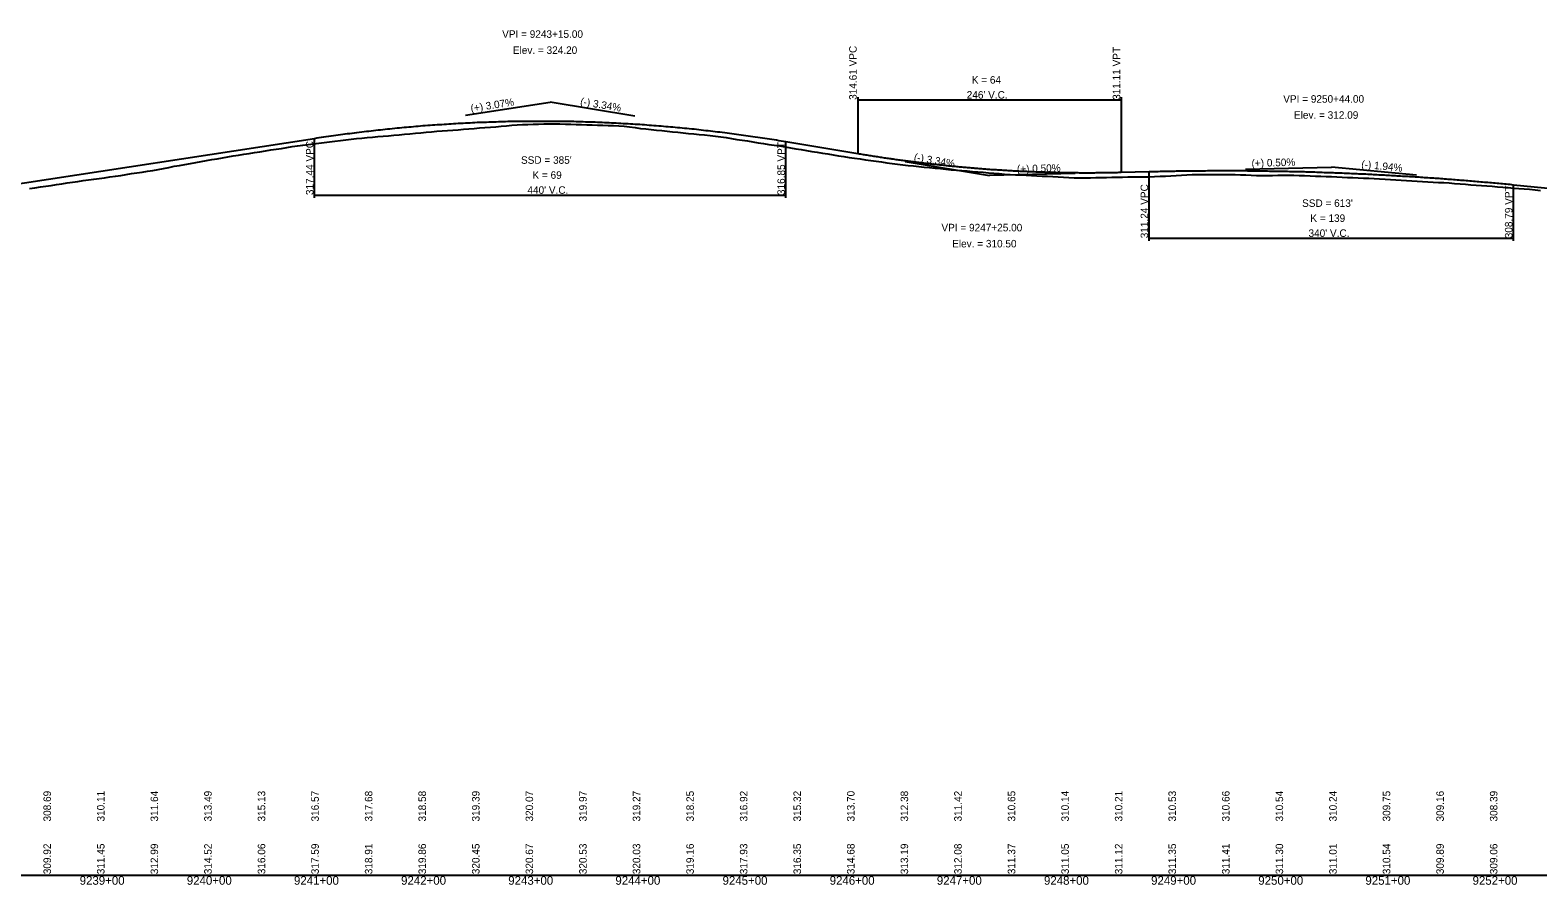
# Model space of a CAD drawing. Extents: x 1838386 to 1955906, y 719739 to 834437.
# Drawn here: x 1918084 to 1919492, y 738480 to 739277 of the extents above; entities that cross this region are included whole.
import ezdxf

# ---------------------------------------------------------------- set-up
doc = ezdxf.new("R2010")
doc.units = 0
for name, color, linetype in [('RD_DDB_GradeTX', 7, 'Continuous'), ('RD_DDB_Profile_EX', 7, 'Continuous'), ('RD_DDB_Profile_Lbl', 7, 'Continuous'), ('RD_DDB_Profile_PR', 7, 'Continuous'), ('RD_DDB_StaTX', 7, 'Continuous'), ('RD_DDB_StripGrade', 7, 'Continuous'), ('RD_DDB_VCLbl', 7, 'Continuous'), ('RD_GPK_Profile_Cell', 7, 'Continuous')]:
    doc.layers.add(name, color=color, linetype=linetype)

msp = doc.modelspace()

# ---------------------------------------------------------------- linework, layer by layer
at = {"layer": 'RD_DDB_GradeTX'}
for p, q in [((1918490.8, 739198), (1918569.9, 739210.1)), ((1918648.8, 739196.9), (1918569.9, 739210.1)), ((1918901, 739154.8), (1918979.9, 739141.6)), ((1919218.9, 739147.6), (1919298.9, 739149.6)), ((1919378.5, 739141.9), (1919298.9, 739149.6)), ((1919059.9, 739143.6), (1918979.9, 739141.6))]:
    msp.add_line(p, q, dxfattribs=at)
at = {"layer": 'RD_DDB_Profile_EX'}
for points in [[(1918084, 739129.5), (1918089, 739130.2), (1918094, 739131), (1918099, 739131.7), (1918104, 739132.5), (1918109, 739133.2), (1918114, 739133.9), (1918119, 739134.7), (1918124, 739135.4), (1918129, 739136.1), (1918134, 739136.9), (1918139, 739137.6), (1918144, 739138.4), (1918149, 739139), (1918154, 739139.6), (1918159, 739140.3), (1918164, 739141.1), (1918169, 739141.8), (1918174, 739142.6), (1918179, 739143.4), (1918184, 739144.1), (1918189, 739144.9), (1918194, 739145.6), (1918199, 739146.3), (1918204, 739147.2), (1918209, 739148.2), (1918214, 739149.2), (1918219, 739150.3), (1918224, 739151.1), (1918229, 739152), (1918234, 739152.9), (1918239, 739153.8), (1918244, 739154.7), (1918249, 739155.6), (1918254, 739156.5), (1918259, 739157.3), (1918264, 739158.2), (1918269, 739159.1), (1918274, 739159.9), (1918279, 739160.7), (1918284, 739161.5), (1918289, 739162.3), (1918294, 739163.1), (1918299, 739163.9), (1918304, 739164.7), (1918309, 739165.5), (1918314, 739166.2), (1918319, 739167), (1918324, 739167.8), (1918329, 739168.6), (1918334, 739169.4), (1918339, 739170.1), (1918344, 739170.7), (1918349, 739171.3), (1918354, 739171.9), (1918359, 739172.5), (1918364, 739173.1), (1918369, 739173.7), (1918374, 739174.3), (1918379, 739174.9), (1918384, 739175.5), (1918389, 739176.1), (1918394, 739176.5), (1918399, 739177), (1918404, 739177.4), (1918409, 739177.9), (1918414, 739178.3), (1918419, 739178.8), (1918424, 739179.3), (1918429, 739179.7), (1918434, 739180.2), (1918439, 739180.6), (1918444, 739181.1), (1918449, 739181.5), (1918454, 739182), (1918459, 739182.4), (1918464, 739182.9), (1918469, 739183.3), (1918474, 739183.7), (1918479, 739184.1), (1918484, 739184.4), (1918489, 739184.8), (1918494, 739185.2), (1918499, 739185.6), (1918504, 739186), (1918509, 739186.4), (1918514, 739186.8), (1918519, 739187.2), (1918524, 739187.6), (1918529, 739188.1), (1918534, 739188.7), (1918539, 739189), (1918544, 739189.1)], [(1918544, 739189.1), (1918549, 739189.3), (1918554, 739189.5), (1918559, 739189.6), (1918564, 739189.8), (1918569, 739189.9), (1918574, 739190), (1918579, 739189.8), (1918584, 739189.7), (1918589, 739189.5), (1918594, 739189.3), (1918599, 739189.2), (1918604, 739189), (1918609, 739188.8), (1918614, 739188.7), (1918619, 739188.5), (1918624, 739188.3), (1918629, 739188.2), (1918634, 739188), (1918639, 739187.8), (1918644, 739187.2), (1918649, 739186.3), (1918654, 739185.6), (1918659, 739185.1), (1918664, 739184.6), (1918669, 739184.1), (1918674, 739183.6), (1918679, 739183), (1918684, 739182.5), (1918689, 739182), (1918694, 739181.5), (1918699, 739181), (1918704, 739180.5), (1918709, 739180), (1918714, 739179.5), (1918719, 739178.9), (1918724, 739178.4), (1918729, 739177.7), (1918734, 739177), (1918739, 739176.2), (1918744, 739175.4), (1918749, 739174.6), (1918754, 739173.9), (1918759, 739173.1), (1918764, 739172.3), (1918769, 739171.5), (1918774, 739170.7), (1918779, 739169.9), (1918784, 739169.2), (1918789, 739168.4), (1918794, 739167.6), (1918799, 739166.7), (1918804, 739165.9), (1918809, 739165.1), (1918814, 739164.2), (1918819, 739163.4), (1918824, 739162.6), (1918829, 739161.8), (1918834, 739160.9), (1918839, 739160.1), (1918844, 739159.3), (1918849, 739158.5), (1918854, 739157.8), (1918859, 739157.1), (1918864, 739156.4), (1918869, 739155.7), (1918874, 739155), (1918879, 739154.3), (1918884, 739153.6), (1918889, 739152.9), (1918894, 739152.2), (1918899, 739151.6), (1918904, 739151.1), (1918909, 739150.6), (1918914, 739150.1), (1918919, 739149.6), (1918924, 739149.1), (1918929, 739148.6), (1918934, 739148.1), (1918939, 739147.5), (1918944, 739147.1), (1918949, 739146.7), (1918954, 739146.3), (1918959, 739145.9), (1918964, 739145.5), (1918969, 739145.1), (1918974, 739144.7), (1918979, 739144.2), (1918984, 739143.8), (1918989, 739143.4), (1918994, 739143), (1918999, 739142.7), (1919004, 739142.4), (1919009, 739142.2), (1919014, 739141.9), (1919019, 739141.7), (1919024, 739141.4), (1919029, 739141.2), (1919034, 739140.9), (1919039, 739140.7), (1919044, 739140.4)], [(1919044, 739140.4), (1919049, 739140.1), (1919054, 739139.9), (1919059, 739139.6), (1919064, 739139.4), (1919069, 739139.5), (1919074, 739139.6), (1919079, 739139.7), (1919084, 739139.8), (1919089, 739139.9), (1919094, 739140), (1919099, 739140.1), (1919104, 739140.2), (1919109, 739140.3), (1919114, 739140.3), (1919119, 739140.4), (1919124, 739140.4), (1919129, 739140.5), (1919134, 739140.7), (1919139, 739140.9), (1919144, 739141.2), (1919149, 739141.5), (1919154, 739141.7), (1919159, 739142), (1919164, 739142.3), (1919169, 739142.5), (1919174, 739142.7), (1919179, 739142.7), (1919184, 739142.6), (1919189, 739142.6), (1919194, 739142.6), (1919199, 739142.5), (1919204, 739142.5), (1919209, 739142.5), (1919214, 739142.4), (1919219, 739142.2), (1919224, 739142), (1919229, 739141.8), (1919234, 739141.7), (1919239, 739141.8), (1919244, 739141.8), (1919249, 739141.9), (1919254, 739141.9), (1919259, 739141.9), (1919264, 739141.9), (1919269, 739141.8), (1919274, 739141.6), (1919279, 739141.4), (1919284, 739141.2), (1919289, 739141), (1919294, 739140.8), (1919299, 739140.6), (1919304, 739140.4), (1919309, 739140.2), (1919314, 739139.9), (1919319, 739139.7), (1919324, 739139.5), (1919329, 739139.3), (1919334, 739139.1), (1919339, 739138.8), (1919344, 739138.5), (1919349, 739138.2), (1919354, 739138), (1919359, 739137.7), (1919364, 739137.4), (1919369, 739137.1), (1919374, 739136.8), (1919379, 739136.5), (1919384, 739136.2), (1919389, 739135.9), (1919394, 739135.6), (1919399, 739135.3), (1919404, 739135), (1919409, 739134.7), (1919414, 739134.3), (1919419, 739133.9), (1919424, 739133.5), (1919429, 739133.1), (1919434, 739132.8), (1919439, 739132.4), (1919444, 739132), (1919449, 739131.6), (1919454, 739131.2), (1919459, 739130.8), (1919464, 739130.4), (1919469, 739130), (1919474, 739129.6), (1919479, 739129.3), (1919484, 739128.8), (1919489, 739128.3), (1919494, 739127.8)]]:
    msp.add_lwpolyline(points, dxfattribs=at)
at = {"layer": 'RD_DDB_Profile_PR'}
for p, q in [((1918029.9, 739127.2), (1918349.9, 739176.3)), ((1918789.9, 739173.4), (1918856.9, 739162.2)), ((1919102.9, 739144.7), (1919128.9, 739145.4)), ((1919468.9, 739133.1), (1919738.9, 739106.9))]:
    msp.add_line(p, q, dxfattribs=at)
for points in [[(1918349.9, 739176.3), (1918358.7, 739177.7), (1918367.5, 739178.9), (1918376.3, 739180.1), (1918385.1, 739181.3), (1918393.9, 739182.4), (1918402.7, 739183.4), (1918411.5, 739184.4), (1918420.3, 739185.3), (1918429.1, 739186.2), (1918437.9, 739187), (1918446.7, 739187.8), (1918455.5, 739188.5), (1918464.3, 739189.1), (1918473.1, 739189.7), (1918481.9, 739190.3), (1918490.7, 739190.7), (1918499.5, 739191.2), (1918508.3, 739191.5), (1918517.1, 739191.8), (1918525.9, 739192.1), (1918534.7, 739192.3), (1918543.5, 739192.4), (1918552.3, 739192.5), (1918561.1, 739192.5), (1918569.9, 739192.5), (1918578.7, 739192.4), (1918587.5, 739192.3), (1918596.3, 739192.1), (1918605.1, 739191.8), (1918613.9, 739191.5), (1918622.7, 739191.1), (1918631.5, 739190.7), (1918640.3, 739190.2), (1918649.1, 739189.7), (1918657.9, 739189.1), (1918666.7, 739188.4), (1918675.5, 739187.7), (1918684.3, 739187), (1918693.1, 739186.1), (1918701.9, 739185.3), (1918710.7, 739184.3), (1918719.5, 739183.3), (1918728.3, 739182.3), (1918737.1, 739181.2), (1918745.9, 739180), (1918754.7, 739178.8), (1918763.5, 739177.5), (1918772.3, 739176.2), (1918781.1, 739174.8), (1918789.9, 739173.4)], [(1918856.9, 739162.2), (1918861.8, 739161.4), (1918866.7, 739160.6), (1918871.6, 739159.8), (1918876.6, 739159.1), (1918881.5, 739158.3), (1918886.4, 739157.6), (1918891.3, 739156.9), (1918896.2, 739156.2), (1918901.2, 739155.6), (1918906.1, 739154.9), (1918911, 739154.3), (1918915.9, 739153.7), (1918920.8, 739153.1), (1918925.8, 739152.5), (1918930.7, 739152), (1918935.6, 739151.5), (1918940.5, 739150.9), (1918945.4, 739150.5), (1918950.4, 739150), (1918955.3, 739149.5), (1918960.2, 739149.1), (1918965.1, 739148.7), (1918970, 739148.3), (1918975, 739147.9), (1918979.9, 739147.5), (1918984.8, 739147.2), (1918989.7, 739146.9), (1918994.6, 739146.6), (1918999.6, 739146.3), (1919004.5, 739146), (1919009.4, 739145.8), (1919014.3, 739145.6), (1919019.2, 739145.4), (1919024.2, 739145.2), (1919029.1, 739145), (1919034, 739144.8), (1919038.9, 739144.7), (1919043.8, 739144.6), (1919048.8, 739144.5), (1919053.7, 739144.4), (1919058.6, 739144.4), (1919063.5, 739144.3), (1919068.4, 739144.3), (1919073.4, 739144.3), (1919078.3, 739144.3), (1919083.2, 739144.4), (1919088.1, 739144.4), (1919093, 739144.5), (1919098, 739144.6), (1919102.9, 739144.7)], [(1919128.9, 739145.4), (1919135.7, 739145.5), (1919142.5, 739145.7), (1919149.3, 739145.8), (1919156.1, 739145.9), (1919162.9, 739146), (1919169.7, 739146.1), (1919176.5, 739146.1), (1919183.3, 739146.2), (1919190.1, 739146.2), (1919196.9, 739146.2), (1919203.7, 739146.2), (1919210.5, 739146.2), (1919217.3, 739146.2), (1919224.1, 739146.1), (1919230.9, 739146), (1919237.7, 739145.9), (1919244.5, 739145.8), (1919251.3, 739145.7), (1919258.1, 739145.6), (1919264.9, 739145.4), (1919271.7, 739145.3), (1919278.5, 739145.1), (1919285.3, 739144.9), (1919292.1, 739144.6), (1919298.9, 739144.4), (1919305.7, 739144.2), (1919312.5, 739143.9), (1919319.3, 739143.6), (1919326.1, 739143.3), (1919332.9, 739143), (1919339.7, 739142.6), (1919346.5, 739142.3), (1919353.3, 739141.9), (1919360.1, 739141.5), (1919366.9, 739141.1), (1919373.7, 739140.7), (1919380.5, 739140.3), (1919387.3, 739139.8), (1919394.1, 739139.4), (1919400.9, 739138.9), (1919407.7, 739138.4), (1919414.5, 739137.9), (1919421.3, 739137.3), (1919428.1, 739136.8), (1919434.9, 739136.2), (1919441.7, 739135.6), (1919448.5, 739135), (1919455.3, 739134.4), (1919462.1, 739133.8), (1919468.9, 739133.1)]]:
    msp.add_spline(points, degree=3, dxfattribs=at)
at = {"layer": 'RD_DDB_VCLbl'}
for p, q in [((1918856.9, 739214.7), (1918856.9, 739162.2)), ((1918856.9, 739212.2), (1919102.9, 739212.2)), ((1919102.9, 739214.7), (1919102.9, 739144.7)), ((1918349.9, 739120.9), (1918349.9, 739176.3)), ((1918789.9, 739120.9), (1918789.9, 739173.4)), ((1919128.9, 739080.6), (1919128.9, 739145.4)), ((1918349.9, 739123.4), (1918789.9, 739123.4)), ((1919468.9, 739080.6), (1919468.9, 739133.1)), ((1919128.9, 739083.1), (1919468.9, 739083.1))]:
    msp.add_line(p, q, dxfattribs=at)
at = {"layer": 'RD_GPK_Profile_Cell'}
msp.add_line((1914544, 738489.1), (1925344, 738489.1), dxfattribs=at)

# ---------------------------------------------------------------- texts
at = {"layer": 'RD_DDB_GradeTX'}
for s, rotation, p in [('(+) 3.07%', 8.7306, (1918496.1, 739200.8)), ('(-) 3.34%', 350.517, (1918597.5, 739207.5)), ('(-) 3.34%', 350.517, (1918908.9, 739155.5)), ('(+) 0.50%', 1.4273, (1919005.5, 739144.3)), ('(+) 0.50%', 1.4273, (1919224.5, 739149.7)), ('(-) 1.94%', 354.4611, (1919326.6, 739148.9))]:
    msp.add_text(s, height=7, rotation=rotation, dxfattribs=at).set_placement(p)
at = {"layer": 'RD_DDB_Profile_Lbl'}
for s, p in [('VPI = 9243+15.00', (1918525, 739270.1)), ('Elev. = 324.20', (1918535, 739255.1)), ('VPI = 9250+44.00', (1919254, 739209.6)), ('Elev. = 312.09', (1919264, 739194.6)), ('VPI = 9247+25.00', (1918935, 739089.6)), ('Elev. = 310.50', (1918945, 739074.6))]:
    msp.add_text(s, height=7, dxfattribs=at).set_placement(p)
at = {"layer": 'RD_DDB_StaTX'}
for s, p in [('9239+00', (1918130.7, 738480.1)), ('9240+00', (1918230.7, 738480.1)), ('9241+00', (1918330.7, 738480.1)), ('9242+00', (1918430.7, 738480.1)), ('9243+00', (1918530.7, 738480.1)), ('9244+00', (1918630.7, 738480.1)), ('9245+00', (1918730.7, 738480.1)), ('9246+00', (1918830.7, 738480.1)), ('9247+00', (1918930.7, 738480.1)), ('9248+00', (1919030.7, 738480.1)), ('9249+00', (1919130.7, 738480.1)), ('9250+00', (1919230.7, 738480.1)), ('9251+00', (1919330.7, 738480.1)), ('9252+00', (1919430.7, 738480.1))]:
    msp.add_text(s, height=8, dxfattribs=at).set_placement(p)
at = {"layer": 'RD_DDB_StripGrade'}
for s, p in [('314.61 VPC', (1918855.9, 739212.2)), ('311.11 VPT', (1919101.9, 739212.2)), ('317.44 VPC', (1918348.9, 739123.4)), ('316.85 VPT', (1918788.9, 739123.4)), ('311.24 VPC', (1919127.9, 739083.1)), ('308.79 VPT', (1919467.9, 739083.1)), ('308.69', (1918103.9, 738539.1)), ('310.11', (1918153.9, 738539.1)), ('311.64', (1918203.9, 738539.1)), ('313.49', (1918253.9, 738539.1)), ('315.13', (1918303.9, 738539.1)), ('316.57', (1918353.9, 738539.1)), ('317.68', (1918403.9, 738539.1)), ('318.58', (1918453.9, 738539.1)), ('319.39', (1918503.9, 738539.1)), ('320.07', (1918553.9, 738539.1)), ('319.97', (1918603.9, 738539.1)), ('319.27', (1918653.9, 738539.1)), ('318.25', (1918703.9, 738539.1)), ('316.92', (1918753.9, 738539.1)), ('315.32', (1918803.9, 738539.1)), ('313.70', (1918853.9, 738539.1)), ('312.38', (1918903.9, 738539.1)), ('311.42', (1918953.9, 738539.1)), ('310.65', (1919003.9, 738539.1)), ('310.14', (1919053.9, 738539.1)), ('310.21', (1919103.9, 738539.1)), ('310.53', (1919153.9, 738539.1)), ('310.66', (1919203.9, 738539.1)), ('310.54', (1919253.9, 738539.1)), ('310.24', (1919303.9, 738539.1)), ('309.75', (1919353.9, 738539.1)), ('309.16', (1919403.9, 738539.1)), ('308.39', (1919453.9, 738539.1)), ('309.92', (1918103.9, 738489.9)), ('311.45', (1918153.9, 738489.9)), ('312.99', (1918203.9, 738489.9)), ('314.52', (1918253.9, 738489.9)), ('316.06', (1918303.9, 738489.9)), ('317.59', (1918353.9, 738489.9)), ('318.91', (1918403.9, 738489.9)), ('319.86', (1918453.9, 738489.9)), ('320.45', (1918503.9, 738489.9)), ('320.67', (1918553.9, 738489.9)), ('320.53', (1918603.9, 738489.9)), ('320.03', (1918653.9, 738489.9)), ('319.16', (1918703.9, 738489.9)), ('317.93', (1918753.9, 738489.9)), ('316.35', (1918803.9, 738489.9)), ('314.68', (1918853.9, 738489.9)), ('313.19', (1918903.9, 738489.9)), ('312.08', (1918953.9, 738489.9)), ('311.37', (1919003.9, 738489.9)), ('311.05', (1919053.9, 738489.9)), ('311.12', (1919103.9, 738489.9)), ('311.35', (1919153.9, 738489.9)), ('311.41', (1919203.9, 738489.9)), ('311.30', (1919253.9, 738489.9)), ('311.01', (1919303.9, 738489.9)), ('310.54', (1919353.9, 738489.9)), ('309.89', (1919403.9, 738489.9)), ('309.06', (1919453.9, 738489.9))]:
    msp.add_text(s, height=7, rotation=90, dxfattribs=at).set_placement(p)
at = {"layer": 'RD_DDB_VCLbl'}
for s, p in [('K = 64', (1918963.3, 739227.4)), ("246' V.C.", (1918958.6, 739213.4)), ("SSD = 385'", (1918542.6, 739152.6)), ('K = 69', (1918553.3, 739138.6)), ("440' V.C.", (1918548.6, 739124.6)), ("SSD = 613'", (1919271.6, 739112.4)), ('K = 139', (1919279.3, 739098.4)), ("340' V.C.", (1919277.6, 739084.4))]:
    msp.add_text(s, height=7, dxfattribs=at).set_placement(p)

doc.saveas('drawing.dxf')
